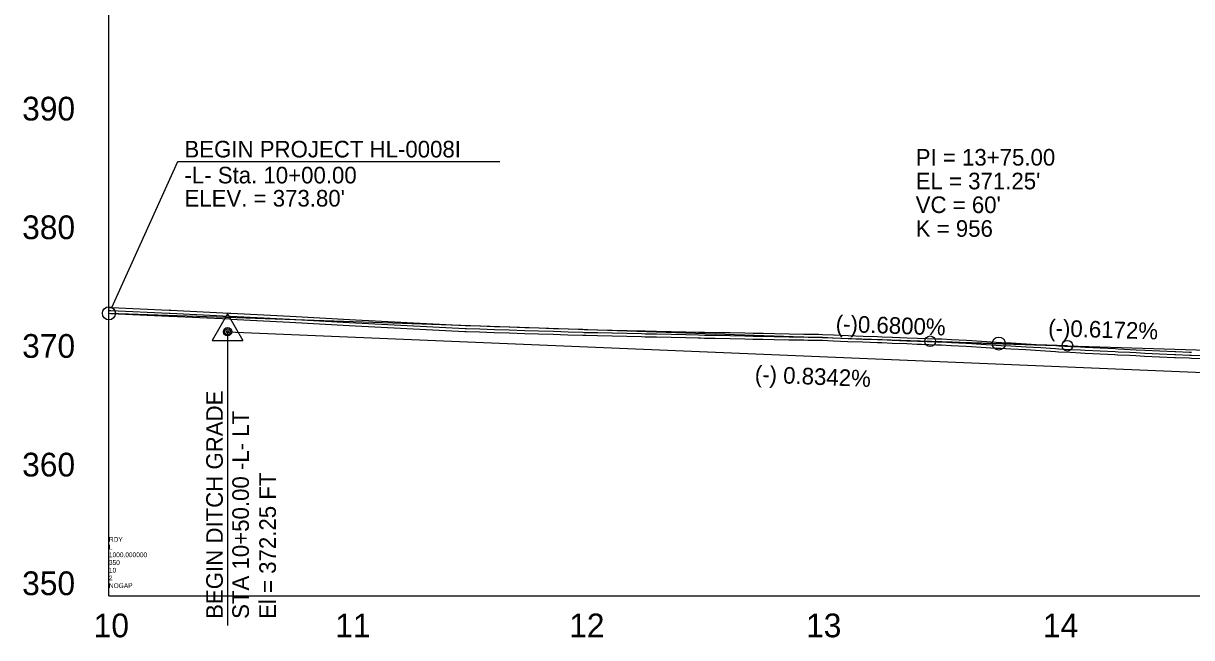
# Model space of a CAD drawing. Extents: x 1625686 to 1640492, y 1161393 to 1175642.
# Drawn here: x 1630168.3 to 1630660.6, y 1174893.1 to 1175152 of the extents above; entities that cross this region are included whole.
import ezdxf

# ---------------------------------------------------------------- set-up
doc = ezdxf.new("R2010")
doc.units = 0
for name, color, linetype in [('Exist Profile Cell', 7, 'Continuous'), ('Exist Vertical Profile Ground Line', 7, 'Continuous'), ('Exist Vertical Profile Horizontal Axis Label Major', 7, 'Continuous'), ('Exist Vertical Profile Vertical Axis Label', 7, 'Continuous'), ('Prop Vertical Profile Curve Label', 7, 'Continuous'), ('Prop Vertical Profile Ditch Grade Left', 7, 'Continuous'), ('Prop Vertical Profile Ditch Grade Left Label', 7, 'Continuous'), ('Prop Vertical Profile Grade', 7, 'Continuous'), ('Prop Vertical Profile Grade Label', 7, 'Continuous'), ('Prop VPI Ditch Grade Left Label', 7, 'Continuous'), ('Prop VPI Label', 7, 'Continuous'), ('Scratch_Level_1', 7, 'Continuous'), ('Scratch_Level_3', 7, 'Continuous'), ('Scratch_Level_5', 7, 'Continuous')]:
    doc.layers.add(name, color=color, linetype=linetype)

msp = doc.modelspace()

# ---------------------------------------------------------------- linework, layer by layer
at = {"layer": 'Exist Profile Cell'}
for q in [(1630204.31, 1175410.79), (1634670.63, 1174910.79), (1630204.31, 1174910.79)]:
    msp.add_line((1630204.31, 1174910.79), q, dxfattribs=at)
at = {"layer": 'Exist Vertical Profile Ground Line'}
msp.add_lwpolyline([(1630204.31, 1175029.8), (1630205.09, 1175029.76), (1630229.6, 1175028.61), (1630230.08, 1175028.59), (1630255.08, 1175027.41), (1630255.52, 1175027.39), (1630280.52, 1175026.06), (1630305.52, 1175024.73), (1630329.89, 1175023.46), (1630354.31, 1175022.19), (1630354.89, 1175022.16), (1630360.52, 1175021.98), (1630366.73, 1175021.78), (1630372.94, 1175021.58), (1630379.52, 1175021.36), (1630385.36, 1175021.17), (1630391.57, 1175020.97), (1630397.77, 1175020.76), (1630403.98, 1175020.55), (1630404.52, 1175020.53), (1630405.26, 1175020.52), (1630410.19, 1175020.4), (1630416.4, 1175020.26), (1630422.61, 1175020.12), (1630428.82, 1175019.98), (1630430.27, 1175019.95), (1630435.02, 1175019.84), (1630441.23, 1175019.69), (1630447.44, 1175019.55), (1630452.7, 1175019.42), (1630453.65, 1175019.4), (1630455.28, 1175019.37), (1630459.86, 1175019.28), (1630466.07, 1175019.16), (1630472.28, 1175019.04), (1630475.74, 1175018.97), (1630478.48, 1175018.93), (1630479.94, 1175018.9), (1630484.69, 1175018.81), (1630490.9, 1175018.69), (1630497.11, 1175018.57), (1630498.92, 1175018.53), (1630503.32, 1175018.46), (1630505, 1175018.43), (1630509.53, 1175018.24), (1630515.74, 1175017.98), (1630522.09, 1175017.71), (1630528.15, 1175017.51), (1630530.06, 1175017.45), (1630534.36, 1175017.27), (1630540.57, 1175017.01), (1630545, 1175016.82), (1630546.78, 1175016.77), (1630553.05, 1175016.57), (1630555.2, 1175016.5), (1630559.31, 1175016.28), (1630565.58, 1175015.95), (1630567.87, 1175015.82), (1630571.85, 1175015.57), (1630578.12, 1175015.18), (1630580.26, 1175015.05), (1630584.39, 1175014.82), (1630590.77, 1175014.48), (1630596.92, 1175014.09), (1630603.19, 1175013.69), (1630604.5, 1175013.61), (1630609.46, 1175013.36), (1630613.71, 1175013.14), (1630615.72, 1175013.04), (1630621.99, 1175012.73), (1630628.26, 1175012.42), (1630629.51, 1175012.36), (1630634.53, 1175012.11), (1630637.15, 1175011.98), (1630640.79, 1175011.8), (1630647.06, 1175011.49), (1630653.33, 1175011.19), (1630653.87, 1175011.16), (1630659.6, 1175010.98), (1630660.52, 1175010.95), (1630665.87, 1175010.76)], dxfattribs=at)
at = {"layer": 'Prop Vertical Profile Curve Label'}
for centre in [(1630550.39, 1175018.02), (1630608.23, 1175016.14)]:
    msp.add_circle(centre, 2.25, dxfattribs=at)
at = {"layer": 'Prop Vertical Profile Ditch Grade Left'}
msp.add_lwpolyline([(1630254.31, 1175022.04), (1630793.74, 1174999.54), (1630854.31, 1175007.09), (1631004.31, 1175017.04)], dxfattribs=at)
at = {"layer": 'Prop Vertical Profile Grade'}
for p, q in [((1630204.31, 1175029.79), (1630550.39, 1175018.02)), ((1630608.23, 1175016.14), (1630764.31, 1175011.33))]:
    msp.add_line(p, q, dxfattribs=at)
msp.add_spline([(1630550.39, 1175018.02), (1630551.55, 1175017.98), (1630552.71, 1175017.94), (1630553.86, 1175017.9), (1630555.02, 1175017.86), (1630556.18, 1175017.82), (1630557.33, 1175017.79), (1630558.49, 1175017.75), (1630559.65, 1175017.71), (1630560.8, 1175017.67), (1630561.96, 1175017.63), (1630563.12, 1175017.59), (1630564.28, 1175017.55), (1630565.43, 1175017.52), (1630566.59, 1175017.48), (1630567.75, 1175017.44), (1630568.9, 1175017.4), (1630570.06, 1175017.36), (1630571.22, 1175017.32), (1630572.37, 1175017.29), (1630573.53, 1175017.25), (1630574.69, 1175017.21), (1630575.84, 1175017.17), (1630577, 1175017.14), (1630578.16, 1175017.1), (1630579.31, 1175017.06), (1630580.47, 1175017.02), (1630581.63, 1175016.99), (1630582.78, 1175016.95), (1630583.94, 1175016.91), (1630585.1, 1175016.87), (1630586.25, 1175016.84), (1630587.41, 1175016.8), (1630588.57, 1175016.76), (1630589.73, 1175016.73), (1630590.88, 1175016.69), (1630592.04, 1175016.65), (1630593.2, 1175016.62), (1630594.35, 1175016.58), (1630595.51, 1175016.54), (1630596.67, 1175016.51), (1630597.82, 1175016.47), (1630598.98, 1175016.43), (1630600.14, 1175016.4), (1630601.29, 1175016.36), (1630602.45, 1175016.32), (1630603.61, 1175016.29), (1630604.76, 1175016.25), (1630605.92, 1175016.22), (1630607.08, 1175016.18), (1630608.23, 1175016.14)], degree=3, dxfattribs=at)
at = {"layer": 'Prop VPI Ditch Grade Left Label'}
for p, q in [((1630254.31, 1175029.52), (1630247.86, 1175018.32)), ((1630254.31, 1175029.52), (1630260.81, 1175018.32)), ((1630254.31, 1175022.04), (1630254.31, 1174898.22)), ((1630247.86, 1175018.32), (1630260.81, 1175018.32))]:
    msp.add_line(p, q, dxfattribs=at)
for radius in [1.75, 1.2, 0.5]:
    msp.add_circle((1630254.31, 1175022.04), radius, dxfattribs=at)
at = {"layer": 'Prop VPI Label'}
for p, q in [((1630205.5, 1175032.27), (1630233.3, 1175093.75)), ((1630233.3, 1175093.75), (1630369.01, 1175093.75)), ((1630550.39, 1175018.02), (1630576.57, 1175017.13)), ((1630608.23, 1175016.14), (1630582.06, 1175016.95))]:
    msp.add_line(p, q, dxfattribs=at)
for centre in [(1630204.31, 1175029.79), (1630579.31, 1175017.04)]:
    msp.add_circle(centre, 2.75, dxfattribs=at)
at = {"layer": 'Scratch_Level_1'}
for p, q in [((1630204.43, 1175032.3), (1630205.2, 1175032.26)), ((1630204.37, 1175031.05), (1630205.15, 1175031.01)), ((1630230.14, 1175029.83), (1630255.14, 1175028.66)), ((1630230.2, 1175031.08), (1630255.19, 1175029.91)), ((1630360.56, 1175023.23), (1630366.77, 1175023.03)), ((1630360.6, 1175024.48), (1630366.81, 1175024.28)), ((1630366.77, 1175023.03), (1630372.98, 1175022.83)), ((1630366.81, 1175024.28), (1630373.02, 1175024.08)), ((1630372.98, 1175022.83), (1630379.56, 1175022.61)), ((1630373.02, 1175024.08), (1630379.6, 1175023.86)), ((1630379.56, 1175022.61), (1630385.4, 1175022.42)), ((1630379.6, 1175023.86), (1630385.44, 1175023.67)), ((1630385.4, 1175022.42), (1630391.61, 1175022.21)), ((1630385.44, 1175023.67), (1630391.65, 1175023.46)), ((1630391.61, 1175022.21), (1630397.82, 1175022.01)), ((1630391.65, 1175023.46), (1630397.86, 1175023.26)), ((1630397.82, 1175022.01), (1630404.02, 1175021.8)), ((1630397.86, 1175023.26), (1630404.07, 1175023.05)), ((1630405.32, 1175023.02), (1630410.25, 1175022.9)), ((1630410.25, 1175022.9), (1630416.46, 1175022.76)), ((1630416.46, 1175022.76), (1630422.67, 1175022.62)), ((1630430.32, 1175022.45), (1630435.08, 1175022.34)), ((1630435.08, 1175022.34), (1630441.29, 1175022.19)), ((1630441.29, 1175022.19), (1630447.5, 1175022.05)), ((1630405.29, 1175021.77), (1630410.22, 1175021.65)), ((1630410.22, 1175021.65), (1630416.43, 1175021.51)), ((1630416.43, 1175021.51), (1630422.64, 1175021.37)), ((1630430.3, 1175021.2), (1630435.05, 1175021.09)), ((1630435.05, 1175021.09), (1630441.26, 1175020.94)), ((1630441.26, 1175020.94), (1630447.47, 1175020.8)), ((1630459.88, 1175020.53), (1630466.09, 1175020.41)), ((1630459.91, 1175021.78), (1630466.12, 1175021.66)), ((1630466.09, 1175020.41), (1630472.3, 1175020.29)), ((1630466.12, 1175021.66), (1630472.33, 1175021.54)), ((1630478.5, 1175020.18), (1630479.96, 1175020.15)), ((1630478.52, 1175021.43), (1630479.98, 1175021.4)), ((1630479.96, 1175020.15), (1630484.72, 1175020.06)), ((1630479.98, 1175021.4), (1630484.74, 1175021.31)), ((1630484.72, 1175020.06), (1630490.93, 1175019.94)), ((1630484.74, 1175021.31), (1630490.95, 1175021.19)), ((1630490.93, 1175019.94), (1630497.14, 1175019.82)), ((1630490.95, 1175021.19), (1630497.16, 1175021.07)), ((1630503.34, 1175019.71), (1630505.02, 1175019.68)), ((1630503.36, 1175020.96), (1630505.04, 1175020.93)), ((1630505.05, 1175019.68), (1630509.58, 1175019.49)), ((1630505.1, 1175020.93), (1630509.63, 1175020.74)), ((1630509.58, 1175019.49), (1630515.79, 1175019.23)), ((1630509.63, 1175020.74), (1630515.84, 1175020.48)), ((1630528.19, 1175018.76), (1630530.1, 1175018.7)), ((1630528.23, 1175020.01), (1630530.14, 1175019.95)), ((1630530.12, 1175018.7), (1630534.41, 1175018.52)), ((1630530.17, 1175019.95), (1630534.47, 1175019.77)), ((1630534.41, 1175018.52), (1630540.62, 1175018.26)), ((1630534.47, 1175019.77), (1630540.67, 1175019.51)), ((1630553.09, 1175017.82), (1630555.24, 1175017.75)), ((1630553.13, 1175019.07), (1630555.28, 1175019))]:
    msp.add_line(p, q, dxfattribs=at)
for points in [[(1630205.21, 1175032.26), (1630229.71, 1175031.1), (1630230.19, 1175031.08)], [(1630205.15, 1175031.01), (1630229.66, 1175029.86), (1630230.14, 1175029.83)], [(1630255.15, 1175028.66), (1630255.59, 1175028.63), (1630280.58, 1175027.31)], [(1630255.22, 1175029.91), (1630255.66, 1175029.88), (1630280.65, 1175028.56)], [(1630280.58, 1175027.31), (1630305.58, 1175025.98), (1630329.96, 1175024.71)], [(1630280.65, 1175028.56), (1630305.65, 1175027.23), (1630330.02, 1175025.96)], [(1630329.96, 1175024.71), (1630354.38, 1175023.44), (1630354.94, 1175023.41), (1630360.56, 1175023.23)], [(1630330.02, 1175025.96), (1630354.44, 1175024.69), (1630354.99, 1175024.66), (1630360.6, 1175024.48)], [(1630404.07, 1175023.05), (1630404.59, 1175023.03), (1630405.32, 1175023.02)], [(1630422.67, 1175022.62), (1630428.87, 1175022.48), (1630430.32, 1175022.45)], [(1630447.5, 1175022.05), (1630452.75, 1175021.92), (1630455.33, 1175021.87), (1630459.91, 1175021.78)], [(1630404.03, 1175021.8), (1630404.56, 1175021.78), (1630405.29, 1175021.77)], [(1630422.64, 1175021.37), (1630428.84, 1175021.23), (1630430.29, 1175021.2)], [(1630447.47, 1175020.8), (1630452.72, 1175020.67), (1630455.31, 1175020.62), (1630459.88, 1175020.53)], [(1630472.3, 1175020.29), (1630475.77, 1175020.22), (1630478.5, 1175020.18)], [(1630472.33, 1175021.54), (1630475.79, 1175021.47), (1630478.52, 1175021.43)], [(1630497.14, 1175019.82), (1630498.94, 1175019.78), (1630503.34, 1175019.71)], [(1630497.16, 1175021.07), (1630498.96, 1175021.03), (1630503.36, 1175020.96)], [(1630515.79, 1175019.23), (1630522.13, 1175018.96), (1630528.19, 1175018.76)], [(1630515.84, 1175020.48), (1630522.18, 1175020.21), (1630528.23, 1175020.01)], [(1630540.62, 1175018.26), (1630545.04, 1175018.07), (1630553.09, 1175017.82)], [(1630540.67, 1175019.51), (1630545.09, 1175019.32), (1630553.13, 1175019.07)], [(1630555.27, 1175017.75), (1630559.38, 1175017.53), (1630565.65, 1175017.19), (1630567.94, 1175017.07)], [(1630555.34, 1175019), (1630559.45, 1175018.78), (1630565.71, 1175018.44), (1630568.01, 1175018.32)], [(1630567.95, 1175017.07), (1630571.93, 1175016.82), (1630578.2, 1175016.43), (1630580.34, 1175016.29), (1630584.45, 1175016.07), (1630590.84, 1175015.73)], [(1630568.03, 1175018.32), (1630572.01, 1175018.07), (1630578.27, 1175017.67), (1630580.41, 1175017.54), (1630584.52, 1175017.32), (1630590.91, 1175016.98)], [(1630590.85, 1175015.73), (1630597, 1175015.34), (1630603.27, 1175014.94), (1630604.57, 1175014.86), (1630609.52, 1175014.61), (1630613.77, 1175014.39), (1630615.79, 1175014.29), (1630622.05, 1175013.98), (1630628.32, 1175013.67), (1630629.57, 1175013.61)], [(1630590.93, 1175016.97), (1630597.08, 1175016.58), (1630603.35, 1175016.19), (1630604.64, 1175016.11), (1630609.58, 1175015.85), (1630613.83, 1175015.64), (1630615.85, 1175015.54), (1630622.11, 1175015.23), (1630628.38, 1175014.92), (1630629.63, 1175014.86)], [(1630629.57, 1175013.61), (1630634.59, 1175013.36), (1630637.21, 1175013.23), (1630640.86, 1175013.05), (1630647.12, 1175012.74), (1630653.39, 1175012.44), (1630653.92, 1175012.41), (1630659.64, 1175012.23), (1630660.56, 1175012.2)], [(1630629.64, 1175014.86), (1630634.65, 1175014.61), (1630637.28, 1175014.47), (1630640.92, 1175014.3), (1630647.18, 1175013.99), (1630653.45, 1175013.69), (1630653.97, 1175013.66), (1630659.68, 1175013.48), (1630660.6, 1175013.45)], [(1630660.57, 1175012.2), (1630665.91, 1175012), (1630672.18, 1175011.78), (1630678.45, 1175011.55), (1630678.92, 1175011.53), (1630684.71, 1175011.35)]]:
    msp.add_lwpolyline(points, dxfattribs=at)
for centre, radius, start, end in [((1630205.09, 1175029.76), 2.5, 87.2965, 87.3228), ((1630205.09, 1175029.76), 1.25, 87.2965, 87.3228), ((1630230.08, 1175028.59), 1.25, 87.3066, 87.4757), ((1630230.08, 1175028.59), 2.5, 87.3066, 87.4757), ((1630255.08, 1175027.41), 1.25, 86.7617, 87.3066), ((1630255.08, 1175027.41), 2.5, 86.7617, 87.3066), ((1630280.52, 1175026.06), 1.25, 86.9552, 86.9664), ((1630280.52, 1175026.06), 2.5, 86.9552, 86.9664), ((1630329.89, 1175023.46), 1.25, 87.0193, 87.0279), ((1630329.89, 1175023.46), 2.5, 87.0193, 87.0279), ((1630360.52, 1175021.98), 1.25, 88.1429, 88.1513), ((1630360.52, 1175021.98), 2.5, 88.1429, 88.1513), ((1630366.73, 1175021.78), 1.25, 88.1345, 88.1429), ((1630366.73, 1175021.78), 2.5, 88.1345, 88.1429), ((1630372.94, 1175021.58), 1.25, 88.1222, 88.1345), ((1630372.94, 1175021.58), 2.5, 88.1222, 88.1345), ((1630379.52, 1175021.36), 1.25, 88.1101, 88.1222), ((1630379.52, 1175021.36), 2.5, 88.1101, 88.1222), ((1630385.36, 1175021.17), 1.25, 88.1014, 88.1101), ((1630385.36, 1175021.17), 2.5, 88.1014, 88.1101), ((1630391.57, 1175020.97), 1.25, 88.0928, 88.1014), ((1630391.57, 1175020.97), 2.5, 88.0928, 88.1014), ((1630397.77, 1175020.76), 1.25, 88.0822, 88.0928), ((1630397.77, 1175020.76), 2.5, 88.0822, 88.0928), ((1630403.98, 1175020.55), 2.5, 88.0051, 88.0822), ((1630405.26, 1175020.52), 2.5, 88.7009, 88.7649), ((1630410.19, 1175020.4), 2.5, 88.692, 88.7009), ((1630416.4, 1175020.26), 2.5, 88.6831, 88.692), ((1630422.61, 1175020.12), 2.5, 88.6754, 88.6831), ((1630430.27, 1175019.95), 2.5, 88.6823, 88.8092), ((1630435.02, 1175019.84), 2.5, 88.6738, 88.6823), ((1630441.23, 1175019.69), 2.5, 88.6654, 88.6738), ((1630447.44, 1175019.55), 2.5, 88.6569, 88.6654), ((1630403.98, 1175020.55), 1.25, 88.0051, 88.0822), ((1630405.26, 1175020.52), 1.25, 88.7009, 88.7649), ((1630410.19, 1175020.4), 1.25, 88.692, 88.7009), ((1630416.4, 1175020.26), 1.25, 88.6831, 88.692), ((1630422.61, 1175020.12), 1.25, 88.6754, 88.6831), ((1630430.27, 1175019.95), 1.25, 88.6823, 88.8092), ((1630435.02, 1175019.84), 1.25, 88.6738, 88.6823), ((1630441.23, 1175019.69), 1.25, 88.6654, 88.6738), ((1630447.44, 1175019.55), 1.25, 88.6569, 88.6654), ((1630459.86, 1175019.28), 1.25, 88.8841, 88.8921), ((1630459.86, 1175019.28), 2.5, 88.8841, 88.8921), ((1630466.07, 1175019.16), 1.25, 88.876, 88.8841), ((1630466.07, 1175019.16), 2.5, 88.876, 88.8841), ((1630472.28, 1175019.04), 1.25, 88.868, 88.876), ((1630472.28, 1175019.04), 2.5, 88.868, 88.876), ((1630478.48, 1175018.93), 1.25, 89.0797, 89.0871), ((1630478.48, 1175018.93), 2.5, 89.0797, 89.0871), ((1630479.94, 1175018.9), 1.25, 88.8816, 89.0797), ((1630479.94, 1175018.9), 2.5, 88.8816, 89.0797), ((1630484.69, 1175018.81), 1.25, 88.8743, 88.8816), ((1630484.69, 1175018.81), 2.5, 88.8743, 88.8816), ((1630490.9, 1175018.69), 1.25, 88.8669, 88.8743), ((1630490.9, 1175018.69), 2.5, 88.8669, 88.8743), ((1630497.11, 1175018.57), 1.25, 88.8596, 88.8669), ((1630497.11, 1175018.57), 2.5, 88.8596, 88.8669), ((1630503.32, 1175018.46), 1.25, 89.0671, 89.0738), ((1630503.32, 1175018.46), 2.5, 89.0671, 89.0738), ((1630505, 1175018.43), 1.25, 87.5871, 89.0671), ((1630505, 1175018.43), 2.5, 87.5871, 89.0671), ((1630509.53, 1175018.24), 1.25, 87.5805, 87.5871), ((1630509.53, 1175018.24), 2.5, 87.5805, 87.5871), ((1630515.74, 1175017.98), 1.25, 87.5739, 87.5805), ((1630515.74, 1175017.98), 2.5, 87.5739, 87.5805), ((1630528.15, 1175017.51), 1.25, 88.1365, 88.1414), ((1630528.15, 1175017.51), 2.5, 88.1365, 88.1414), ((1630530.06, 1175017.45), 1.25, 87.6088, 88.1365), ((1630530.06, 1175017.45), 2.5, 87.6088, 88.1365), ((1630534.36, 1175017.27), 1.25, 87.604, 87.6088), ((1630534.36, 1175017.27), 2.5, 87.604, 87.6088), ((1630540.57, 1175017.01), 1.25, 87.5992, 87.604), ((1630540.57, 1175017.01), 2.5, 87.5992, 87.604), ((1630553.05, 1175016.57), 1.25, 88.162, 88.1817), ((1630553.05, 1175016.57), 2.5, 88.162, 88.1817), ((1630555.2, 1175016.5), 1.25, 86.9442, 88.162), ((1630555.2, 1175016.5), 2.5, 86.9442, 88.162), ((1630567.87, 1175015.82), 1.25, 86.3968, 86.9502), ((1630567.87, 1175015.82), 2.5, 86.3968, 86.9502), ((1630590.77, 1175014.48), 1.25, 86.3694, 86.9187), ((1630590.77, 1175014.48), 2.5, 86.3694, 86.9187), ((1630629.51, 1175012.36), 1.25, 87.1053, 87.1913), ((1630629.51, 1175012.36), 2.5, 87.1053, 87.1913), ((1630660.52, 1175010.95), 1.25, 87.9027, 88.1863)]:
    msp.add_arc(centre, radius, start, end, dxfattribs=at)
at = {"layer": 'Scratch_Level_3'}
msp.add_lwpolyline([(1630204.31, 1174910.79), (1634341.72, 1174910.79), (1634341.72, 1175362.47)], dxfattribs=at)
at = {"layer": 'Scratch_Level_5'}
msp.add_lwpolyline([(1630204.31, 1175029.8), (1630205.09, 1175029.76), (1630229.6, 1175028.61), (1630230.08, 1175028.59), (1630255.08, 1175027.41), (1630255.52, 1175027.39), (1630280.52, 1175026.06), (1630305.52, 1175024.73), (1630329.89, 1175023.46), (1630354.31, 1175022.19), (1630354.89, 1175022.16), (1630360.52, 1175021.98), (1630366.73, 1175021.78), (1630372.94, 1175021.58), (1630379.52, 1175021.36), (1630385.36, 1175021.17), (1630391.57, 1175020.97), (1630397.77, 1175020.76), (1630403.98, 1175020.55), (1630404.52, 1175020.53), (1630405.26, 1175020.52), (1630410.19, 1175020.4), (1630416.4, 1175020.26), (1630422.61, 1175020.12), (1630428.82, 1175019.98), (1630430.27, 1175019.95), (1630435.02, 1175019.84), (1630441.23, 1175019.69), (1630447.44, 1175019.55), (1630452.7, 1175019.42), (1630453.65, 1175019.4), (1630455.28, 1175019.37), (1630459.86, 1175019.28), (1630466.07, 1175019.16), (1630472.28, 1175019.04), (1630475.74, 1175018.97), (1630478.48, 1175018.93), (1630479.94, 1175018.9), (1630484.69, 1175018.81), (1630490.9, 1175018.69), (1630497.11, 1175018.57), (1630498.92, 1175018.53), (1630503.32, 1175018.46), (1630505, 1175018.43), (1630509.53, 1175018.24), (1630515.74, 1175017.98), (1630522.09, 1175017.71), (1630528.15, 1175017.51), (1630530.06, 1175017.45), (1630534.36, 1175017.27), (1630540.57, 1175017.01), (1630545, 1175016.82), (1630546.78, 1175016.77), (1630553.05, 1175016.57), (1630555.2, 1175016.5), (1630559.31, 1175016.28), (1630565.58, 1175015.95), (1630567.87, 1175015.82), (1630571.85, 1175015.57), (1630578.12, 1175015.18), (1630580.26, 1175015.05), (1630584.39, 1175014.82), (1630590.77, 1175014.48), (1630596.92, 1175014.09), (1630603.19, 1175013.69), (1630604.5, 1175013.61), (1630609.46, 1175013.36), (1630613.71, 1175013.14), (1630615.72, 1175013.04), (1630621.99, 1175012.73), (1630628.26, 1175012.42), (1630629.51, 1175012.36), (1630634.53, 1175012.11), (1630637.15, 1175011.98), (1630640.79, 1175011.8), (1630647.06, 1175011.49), (1630653.33, 1175011.19), (1630653.87, 1175011.16), (1630659.6, 1175010.98), (1630660.52, 1175010.95), (1630665.87, 1175010.76)], dxfattribs=at)

# ---------------------------------------------------------------- texts
at = {"layer": 'Exist Profile Cell'}
for s, p in [('RDY', (1630204.31, 1174933.54)), ('1000.000000', (1630204.31, 1174927.04)), ('L', (1630204.31, 1174930.29)), ('350', (1630204.31, 1174923.79)), ('2', (1630204.31, 1174917.29)), ('10', (1630204.31, 1174920.54)), ('NOGAP', (1630204.31, 1174914.04))]:
    msp.add_text(s, height=2, dxfattribs=at).set_placement(p)
at = {"layer": 'Exist Vertical Profile Horizontal Axis Label Major'}
for s, p in [('10', (1630197.9, 1174893.29)), ('11', (1630299.74, 1174893.29)), ('12', (1630398.29, 1174893.29)), ('13', (1630498.12, 1174893.29)), ('14', (1630597.96, 1174893.29))]:
    msp.add_text(s, height=10, dxfattribs=at).set_placement(p)
at = {"layer": 'Exist Vertical Profile Vertical Axis Label'}
for s, p in [('390', (1630167.75, 1175111.04)), ('380', (1630167.75, 1175061.04)), ('370', (1630167.75, 1175011.04)), ('360', (1630167.75, 1174961.04)), ('350', (1630167.75, 1174911.04))]:
    msp.add_text(s, height=10, dxfattribs=at).set_placement(p)
at = {"layer": 'Prop Vertical Profile Curve Label'}
for s, p in [("VC = 60'", (1630544.31, 1175072.04)), ('K = 956', (1630544.31, 1175062.04))]:
    msp.add_text(s, height=7, dxfattribs=at).set_placement(p)
at = {"layer": 'Prop Vertical Profile Ditch Grade Left Label'}
msp.add_text('(-) 0.8342%', height=7, rotation=357.6115, dxfattribs=at).set_placement((1630476.4, 1175000.76))
at = {"layer": 'Prop Vertical Profile Grade Label'}
for s, rotation, p in [('(-)0.6800%', 358.0528, (1630510.52, 1175022)), ('(-)0.6172%', 358.2325, (1630600.06, 1175020.19))]:
    msp.add_text(s, height=7, rotation=rotation, dxfattribs=at).set_placement(p)
at = {"layer": 'Prop VPI Ditch Grade Left Label'}
for s, p in [('BEGIN DITCH GRADE', (1630252.31, 1174901.04)), ('STA 10+50.00 -L- LT', (1630263.31, 1174901.04)), ('El = 372.25 FT', (1630274.69, 1174901.04))]:
    msp.add_text(s, height=7, rotation=90, dxfattribs=at).set_placement(p)
at = {"layer": 'Prop VPI Label'}
for s, p in [('BEGIN PROJECT HL-0008I', (1630236.14, 1175095.47)), ('PI = 13+75.00', (1630544.31, 1175092.04)), ('-L- Sta. 10+00.00', (1630236.14, 1175084.53)), ("EL = 371.25'", (1630544.31, 1175082.04)), ("ELEV. = 373.80'", (1630236.14, 1175074.78))]:
    msp.add_text(s, height=7, dxfattribs=at).set_placement(p)

doc.saveas('drawing.dxf')
